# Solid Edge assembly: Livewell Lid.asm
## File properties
Author: m_hel
Template: Iso Metric Assembly.asm
Last saved by: m_hel
Revision: 10
Application: Solid Edge
Username: m_hel
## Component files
Livewell Lid.par
Lid Handle.asm
Lid Hinge.asm
Lid Hinge_mir.asm
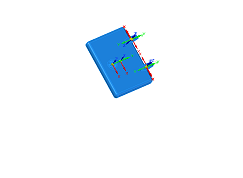
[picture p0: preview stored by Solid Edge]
